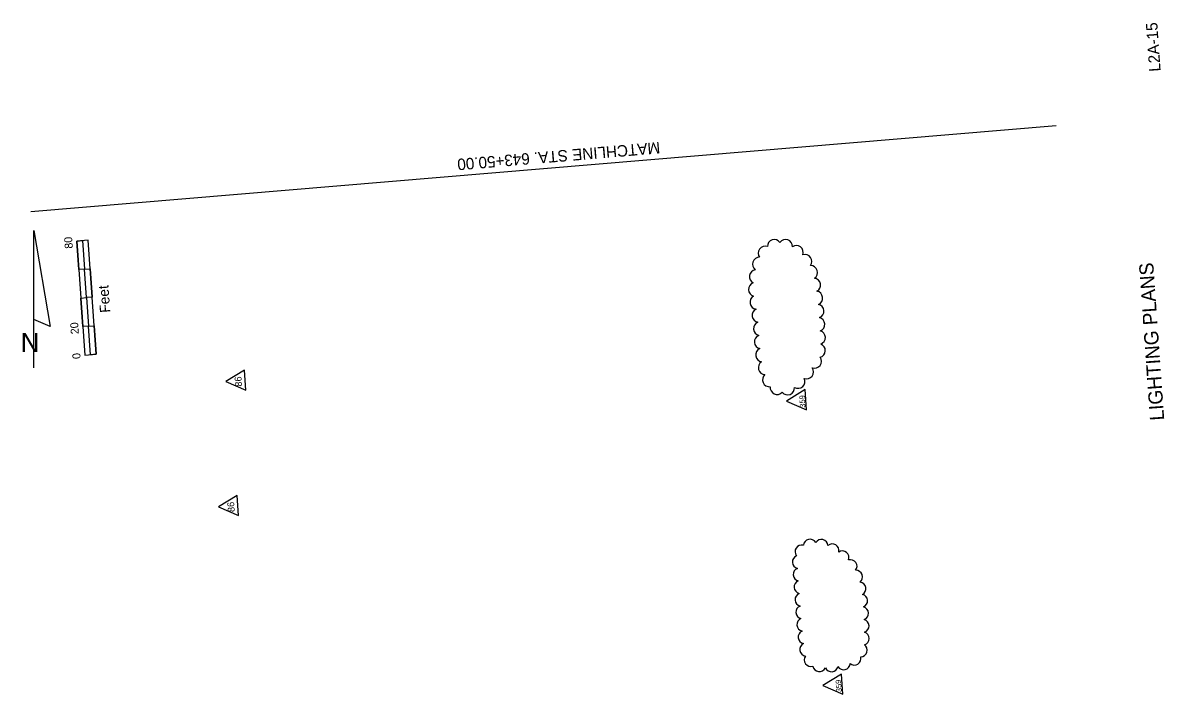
# Model space of a CAD drawing. Extents: x 928662 to 929564, y 639038 to 640295.
# Drawn here: x 928662 to 929460, y 639825 to 640295 of the extents above; entities that cross this region are included whole.
import ezdxf

# ---------------------------------------------------------------- set-up
doc = ezdxf.new("R2010")
doc.units = 0
for name, color, linetype in [('AdhocPoint_dp', 7, 'Continuous'), ('PlotBorder_dp', 7, 'Continuous'), ('ScratchEle_dp', 7, 'Continuous'), ('TextMisc', 7, 'Continuous'), ('TextShtNo', 7, 'Continuous'), ('TextTitle', 7, 'Continuous')]:
    doc.layers.add(name, color=color, linetype=linetype)

msp = doc.modelspace()

# ---------------------------------------------------------------- linework, layer by layer
at = {"layer": 'AdhocPoint_dp'}
msp.add_line((928669.37, 640053.44), (928669.37, 640149.44), dxfattribs=at)
msp.add_lwpolyline([(928669.37, 640087.04), (928669.37, 640149.44), (928680.89, 640082.24)], close=True, dxfattribs=at)
at = {"layer": 'PlotBorder_dp'}
msp.add_lwpolyline([(929384.91, 640222.63), (929026.17, 640192.5), (928667.43, 640162.36)], dxfattribs=at)
at = {"layer": 'ScratchEle_dp'}
for points in [[(928803.74, 640043.78), (928817.76, 640037.7), (928816.77, 640051.75)], [(929196.14, 640030.09), (929210.17, 640024.02), (929209.18, 640038.07)], [(928798.6, 639956.07), (928812.63, 639949.99), (928811.64, 639964.04)], [(929221.56, 639831.13), (929235.58, 639825.05), (929234.59, 639839.1)]]:
    msp.add_lwpolyline(points, close=True, dxfattribs=at)
for centre, radius, start, end in [((929187.65, 640138.22), 4.85, 36.45605, 181.45605), ((929195.45, 640138.21), 4.85, 358.40857, 143.40857), ((929181.23, 640133.5), 4.85, 71.25472, 216.25472), ((929203.04, 640134.07), 4.85, 339.41877, 124.41877), ((929177.2, 640125.78), 4.85, 88.62539, 233.62539), ((929209.08, 640127.75), 4.85, 322.92208, 107.92208), ((929175.04, 640117.07), 4.85, 98.42028, 243.42028), ((929212.97, 640119.97), 4.85, 305.19249, 90.19249), ((929174.46, 640108.14), 4.85, 109.16671, 254.16671), ((929215.19, 640111.18), 4.85, 298.16543, 83.16543), ((929175.44, 640099.2), 4.85, 118.43265, 263.43265), ((929216.59, 640102.13), 4.85, 294.39112, 79.39112), ((929176.96, 640089.99), 4.85, 115.30895, 260.30895), ((929217.5, 640092.98), 4.85, 292.00794, 77.00794), ((929177.93, 640080.69), 4.85, 111.51956, 256.51956), ((929218.13, 640083.77), 4.85, 290.76114, 75.76114), ((929218.52, 640074.56), 4.85, 289.15603, 74.15603), ((929178.58, 640071.46), 4.85, 111.62555, 256.62555), ((929218.44, 640065.42), 4.86, 284.84092, 69.84092), ((929179.56, 640062.36), 4.85, 115.59926, 260.59926), ((929181.32, 640053.44), 4.85, 121.70192, 266.70192), ((929210.2, 640050.49), 4.85, 250.40847, 35.40847), ((929215.75, 640057.89), 4.85, 250.82888, 35.82888), ((929184.24, 640044.94), 4.85, 131.22944, 276.22944), ((929204.19, 640043.84), 4.85, 240.39595, 25.39595), ((929189.58, 640039.5), 4.85, 172.73368, 317.73368), ((929196.95, 640039.29), 4.85, 218.89596, 3.89596), ((929212.58, 639928.78), 4.61, 29.64625, 174.64625), ((929206.75, 639924.76), 4.61, 74.42336, 219.42336), ((929220.54, 639928.67), 4.61, 3.80823, 148.80823), ((929228.22, 639925.53), 4.61, 346.72291, 131.72291), ((929204.88, 639917.54), 4.61, 111.51956, 256.51956), ((929235.25, 639920.62), 4.61, 338.37511, 123.37511), ((929240.91, 639914.51), 4.61, 322.33613, 107.33613), ((929205.49, 639908.76), 4.61, 111.51956, 256.51956), ((929244.8, 639907.08), 4.61, 307.85682, 92.85682), ((929206.11, 639899.98), 4.61, 111.51956, 256.51956), ((929247.1, 639898.85), 4.61, 298.46446, 83.46446), ((929206.73, 639891.2), 4.61, 111.51956, 256.51956), ((929248.3, 639890.29), 4.61, 292.48809, 77.48809), ((929207.36, 639882.42), 4.61, 111.67462, 256.67462), ((929248.93, 639881.56), 4.61, 290.73286, 75.73286), ((929208.05, 639873.66), 4.61, 112.42543, 257.42543), ((929249.32, 639872.8), 4.61, 289.3615, 74.3615), ((929208.91, 639864.93), 4.61, 113.72906, 258.72906), ((929249.4, 639864.06), 4.61, 286.63121, 71.63121), ((929210.08, 639856.29), 4.62, 116.74711, 261.74711), ((929248.09, 639855.85), 4.61, 270.26997, 55.26997), ((929213.17, 639849.03), 4.61, 144.35853, 289.35853), ((929236.13, 639846.78), 4.61, 210.71872, 355.71872), ((929243.66, 639850), 4.61, 230.55531, 15.55531), ((929219.25, 639845.44), 4.61, 189.46011, 334.46011), ((929227.63, 639845.31), 4.61, 203.84085, 348.84085)]:
    msp.add_arc(centre, radius, start, end, dxfattribs=at)
at = {"layer": 'TextTitle'}
for p, q in [((928707.38, 640142.6), (928699.4, 640142.04)), ((928699.4, 640142.04), (928705, 640062.24)), ((928712.98, 640062.8), (928707.38, 640142.6)), ((928705, 640062.24), (928712.98, 640062.8))]:
    msp.add_line(p, q, dxfattribs=at)
for points in [[(928704.79, 640122.37), (928700.8, 640122.09), (928699.4, 640142.04), (928703.39, 640142.32)], [(928710.18, 640102.7), (928706.19, 640102.42), (928704.79, 640122.37), (928708.78, 640122.65)], [(928707.59, 640082.47), (928703.6, 640082.19), (928702.2, 640102.14), (928706.19, 640102.42)], [(928712.98, 640062.8), (928708.99, 640062.52), (928707.59, 640082.47), (928711.58, 640082.75)]]:
    msp.add_lwpolyline(points, close=True, dxfattribs=at)

# ---------------------------------------------------------------- texts
at = {"layer": 'AdhocPoint_dp'}
msp.add_text('N', height=13.43, dxfattribs=at).set_placement((928660.25, 640064.31))
at = {"layer": 'PlotBorder_dp'}
msp.add_text('MATCHLINE STA. 643+50.00', height=8, rotation=184.80152, dxfattribs=at).set_placement((929107.38, 640211.36))
at = {"layer": 'ScratchEle_dp'}
for s, height, p in [('86', 4.8, (928815.16, 640040.31)), ('359', 3.8, (929209.43, 640025.55)), ('86', 4.8, (928810.03, 639952.6)), ('359', 3.8, (929234.85, 639826.59))]:
    msp.add_text(s, height=height, rotation=94.01956, dxfattribs=at).set_placement(p)
at = {"layer": 'TextMisc'}
msp.add_text('     LIGHTING PLANS     ', height=10, rotation=94.01956, dxfattribs=at).set_placement((929461.86, 639998.25))
at = {"layer": 'TextShtNo'}
msp.add_text('L2A-15', height=8, rotation=94.01956, dxfattribs=at).set_placement((929458.03, 640260.78))
at = {"layer": 'TextTitle'}
for s, height, p in [('80', 5.6, (928696.75, 640136.86)), ('Feet', 7.2, (928722.95, 640092.11)), ('20', 5.6, (928700.96, 640077.03)), ('0', 5.6, (928702.17, 640059.71))]:
    msp.add_text(s, height=height, rotation=94.01956, dxfattribs=at).set_placement(p)

doc.saveas('drawing.dxf')
